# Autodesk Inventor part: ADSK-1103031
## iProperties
Shininess: 41.0
Length Units: 11272
Angle Units: 11279
Time Units: 11290
Mass Units: 11286
Length Display Precision: 4
Angle Display Precision: 2
Compacted: True
Created: 2000-08
Part Number: ADSK-1103031
Document SubType Name: Modeling
Description: CLUTCH SHOE
Mass: 1.0536 g
Surface Area: 3.5197 cm^2
Volume: 0.233613 cm^3
Density: 4.51 g/cm^3
Material: Titanium
Density: 0.0
Volumn: 0.0
Area: 0.0
PropertySet Name: Model Information
Control State: 0
Master: False
Checked Out: False
